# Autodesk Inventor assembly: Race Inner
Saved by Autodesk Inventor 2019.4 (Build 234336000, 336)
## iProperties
Created: 2020-05
Part Number: Race Inner
Document SubType Name: Assembly
Designer: Administrator
Title: Race Inner
Author: Administrator
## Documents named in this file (3)
- c:\worker\convert-fusion-r04\tmp\job-1\518\output\files\f72afacd-c456-4141-9509-cc60ea00d29e\Race Inner.iam
- c:\worker\convert-fusion-r04\tmp\job-1\518\output\files\f72afacd-c456-4141-9509-cc60ea00d29e\Race Inner Bottom.ipt
- c:\worker\convert-fusion-r04\tmp\job-1\518\output\files\f72afacd-c456-4141-9509-cc60ea00d29e\Race Inner Top.ipt
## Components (2 placed, 2 different names)
1. Race Inner Bottom:1
2. Race Inner Top:1
